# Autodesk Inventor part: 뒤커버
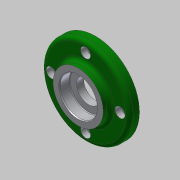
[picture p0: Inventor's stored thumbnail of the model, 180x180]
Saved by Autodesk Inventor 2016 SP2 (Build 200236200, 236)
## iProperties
Created: 2019-01
Part Number: 뒤커버
Material: 알루미늄 6061
Document SubType Name: Modeling
Designer: mduedu
Density: 1 g/cm^3
Appearance: 알루미늄 - 평지
Author: mduedu
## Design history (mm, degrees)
sketch "스케치1"
  geometry: L1 (0, 0)-(6, 0); L2 (6, 0)-(6, 20); L3 (6, 20)-(0, 20); L4 (0, 20)-(0, 0); L5 (6, 0)-(14, 0); L6 (14, 0)-(14, 35); L7 (14, 35)-(6, 35); L8 (6, 35)-(6, 0); L9 (14, 0)-(19, 0); L10 (19, 0)-(19, 20); L11 (19, 20)-(14, 20); L12 (14, 20)-(14, 0)
  constraints: 24 end point, 6 parallel, 3 horizontal, 3 perpendicular
  dimensions: "d6" = 70 diameter of L7 L5; "d8" = 40 diameter of L3 L1; "d9" = 40 diameter of L11 L9; "d10" = 5 distance of L10.end L11.end; "d11" = 6 distance of L2.end L3.end; "d12" = 19 distance between parallel lines of L4 L10; "d13" = 8 distance of L6.end L7.end (derived)
revolve "회전1" sketch "스케치1" stored, may be unused: angle "d5" = 90 deg
sketch "스케치2" dims "d14" = 55
  geometry: 7 further points
  constraints: 2 coincident, 2 vertical alignment, 7 other
  dimensions: "d17" = 360 deg dimension on point (0, 0) point (0, 27.5) (derived)
sketch "스케치3"
  geometry: 4 further points
  constraints: 4 other
hole "구멍1" sketch "스케치3" at (0, 27.5), (-27.5, 0), (27.5, 0), (0, -27.5) diameter "d19" = 4.5; stored, may be unused: countersink angle "d23" = 90 deg, drill point angle "d25" = 0 deg; dims "d20" = 6, "d21" = 8, "d22" = 4.6, "d24" = 8
fillet "모깎기1" dims "d26" = 3
sketch "스케치4"
  geometry: C1 r 9.5 at (0, 0); 1 further point
  constraints: 1 centre point, 1 coincident
  dimensions: "d27" = 19 diameter of C1
extrude "돌출1" cut sketch "스케치4" stored distance "d28" = 10; taper "d29" = 0 deg
sketch "스케치5"
  geometry: C1 r 15 at (0, 0); 1 further point
  constraints: 1 centre point, 1 coincident
  dimensions: "d31" = 30 diameter of C1
extrude "돌출2" cut sketch "스케치5" distance "d32" = 8.3; taper "d33" = 0 deg
chamfer "모따기1" distance "d34" = 0.8; stored, may be unused: second distance "d35" = 2, angle "d36" = 30 deg
fillet "모깎기2" dims "d37" = 3
fillet "모깎기3" dims "d38" = 0.5
sketch "스케치6"
  geometry: C1 r 16.5 at (0, 0); 1 further point
  constraints: 1 centre point, 1 coincident
  dimensions: "d39" = 33 diameter of C1
extrude "돌출3" cut sketch "스케치6" distance "d40" = 5; taper "d41" = 0 deg
fillet "모깎기4" dims "d42" = 3
chamfer "모따기2" distance "d43" = 1; stored, may be unused: second distance "d44" = 2, angle "d45" = 30 deg
node "솔리드1"
